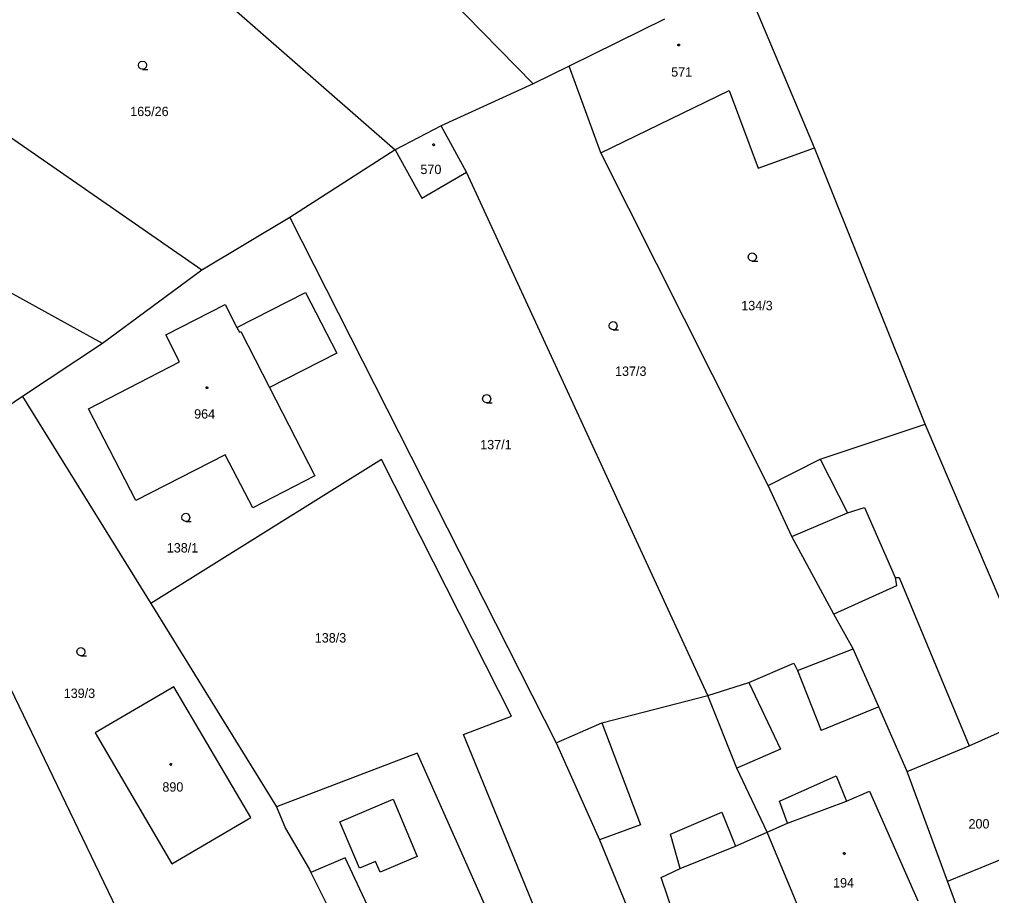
# Model space of a CAD drawing. Extents: x -757994 to -755874, y -1047691 to -1046119.
# Drawn here: x -756617.1 to -756529, y -1046807.2 to -1046727.9 of the extents above; entities that cross this region are included whole.
import ezdxf

# ---------------------------------------------------------------- set-up
doc = ezdxf.new("R2010")
doc.units = 0
doc.layers.add('katastrální mapa', color=7, linetype='Continuous')

msp = doc.modelspace()

# ---------------------------------------------------------------- linework, layer by layer
at = {"layer": 'katastrální mapa'}
for p, q in [((-756606.32, -1046719.31), (-756583.02, -1046739.66)), ((-756581.89, -1046722.04), (-756570.55, -1046733.67)), ((-756545.07, -1046739.46), (-756551.46, -1046724.28)), ((-756558.64, -1046727.81), (-756567.29, -1046732.07)), ((-756567.29, -1046732.07), (-756570.55, -1046733.67)), ((-756564.41, -1046739.94), (-756567.29, -1046732.07)), ((-756570.55, -1046733.67), (-756578.88, -1046737.48)), ((-756600.53, -1046750.55), (-756623.66, -1046734.54)), ((-756564.41, -1046739.94), (-756552.8, -1046734.29)), ((-756552.8, -1046734.29), (-756550.15, -1046741.3)), ((-756578.88, -1046737.48), (-756583.02, -1046739.66)), ((-756576.58, -1046741.67), (-756578.88, -1046737.48)), ((-756583.02, -1046739.66), (-756592.57, -1046745.77)), ((-756583.02, -1046739.66), (-756580.61, -1046744.02)), ((-756550.15, -1046741.3), (-756545.07, -1046739.46)), ((-756535.04, -1046764.48), (-756545.07, -1046739.46)), ((-756549.25, -1046770.05), (-756564.41, -1046739.94)), ((-756580.61, -1046744.02), (-756576.58, -1046741.67)), ((-756554.71, -1046789.06), (-756576.58, -1046741.67)), ((-756609.53, -1046757.2), (-756635.08, -1046743.13)), ((-756592.57, -1046745.77), (-756600.53, -1046750.55)), ((-756592.57, -1046745.77), (-756568.44, -1046793.33)), ((-756600.53, -1046750.55), (-756609.53, -1046757.2)), ((-756597.36, -1046755.74), (-756591.15, -1046752.56)), ((-756591.15, -1046752.56), (-756588.33, -1046758.07)), ((-756603.79, -1046756.41), (-756598.43, -1046753.65)), ((-756598.43, -1046753.65), (-756597.36, -1046755.74)), ((-756602.56, -1046758.86), (-756603.79, -1046756.41)), ((-756597.36, -1046755.74), (-756597.14, -1046756.16)), ((-756597.14, -1046756.16), (-756597, -1046756.09)), ((-756597, -1046756.09), (-756594.4, -1046761.17)), ((-756609.53, -1046757.2), (-756616.78, -1046762)), ((-756588.33, -1046758.07), (-756594.4, -1046761.17)), ((-756610.8, -1046763.1), (-756602.56, -1046758.86)), ((-756594.4, -1046761.17), (-756590.3, -1046769.18)), ((-756616.78, -1046762), (-756624.18, -1046766.9)), ((-756616.78, -1046762), (-756605.17, -1046780.74)), ((-756606.52, -1046771.41), (-756610.8, -1046763.1)), ((-756544.53, -1046767.65), (-756535.04, -1046764.48)), ((-756518.57, -1046803.12), (-756535.04, -1046764.48)), ((-756598.42, -1046767.28), (-756606.52, -1046771.41)), ((-756595.93, -1046772.08), (-756598.42, -1046767.28)), ((-756549.25, -1046770.05), (-756544.53, -1046767.65)), ((-756544.53, -1046767.65), (-756542.08, -1046772.53)), ((-756627.02, -1046769.47), (-756605.13, -1046814.89)), ((-756590.3, -1046769.18), (-756595.93, -1046772.08)), ((-756547.1, -1046774.66), (-756549.25, -1046770.05)), ((-756542.08, -1046772.53), (-756540.52, -1046772.03)), ((-756540.52, -1046772.03), (-756537.75, -1046778.37)), ((-756547.1, -1046774.66), (-756542.08, -1046772.53)), ((-756543.3, -1046781.7), (-756547.1, -1046774.66)), ((-756537.75, -1046778.37), (-756537.39, -1046778.36)), ((-756537.75, -1046778.37), (-756537.64, -1046779.14)), ((-756537.39, -1046778.36), (-756531.04, -1046793.61)), ((-756537.64, -1046779.14), (-756543.3, -1046781.7)), ((-756605.17, -1046780.74), (-756593.77, -1046799.13)), ((-756541.55, -1046784.82), (-756543.3, -1046781.7)), ((-756546.6, -1046786.8), (-756541.55, -1046784.82)), ((-756539.24, -1046790.08), (-756541.55, -1046784.82)), ((-756551, -1046787.88), (-756546.92, -1046786.14)), ((-756546.92, -1046786.14), (-756546.6, -1046786.8)), ((-756546.6, -1046786.8), (-756544.45, -1046792.21)), ((-756603.08, -1046788.27), (-756610.19, -1046792.45)), ((-756596.11, -1046800.11), (-756603.08, -1046788.27)), ((-756554.71, -1046789.06), (-756551, -1046787.88)), ((-756551, -1046787.88), (-756548.13, -1046793.91)), ((-756564.33, -1046791.54), (-756554.71, -1046789.06)), ((-756552.08, -1046795.63), (-756554.71, -1046789.06)), ((-756539.24, -1046790.08), (-756544.45, -1046792.21)), ((-756536.67, -1046795.95), (-756539.24, -1046790.08)), ((-756568.44, -1046793.33), (-756564.33, -1046791.54)), ((-756564.33, -1046791.54), (-756560.81, -1046800.77)), ((-756610.19, -1046792.45), (-756603.25, -1046804.31)), ((-756531.04, -1046793.61), (-756527.33, -1046791.96)), ((-756568.44, -1046793.33), (-756564.54, -1046802.11)), ((-756581.05, -1046794.27), (-756593.77, -1046799.13)), ((-756548.13, -1046793.91), (-756552.08, -1046795.63)), ((-756536.67, -1046795.95), (-756531.04, -1046793.61)), ((-756549.35, -1046801.44), (-756552.08, -1046795.63)), ((-756533.02, -1046805.87), (-756536.67, -1046795.95)), ((-756548.22, -1046798.63), (-756543.11, -1046796.34)), ((-756543.11, -1046796.34), (-756542.17, -1046798.61)), ((-756542.17, -1046798.61), (-756540.07, -1046797.73)), ((-756540.07, -1046797.73), (-756535.71, -1046807.66)), ((-756588.03, -1046800.48), (-756583.2, -1046798.44)), ((-756583.2, -1046798.44), (-756581.04, -1046803.64)), ((-756547.5, -1046800.6), (-756548.22, -1046798.63)), ((-756547.5, -1046800.6), (-756542.17, -1046798.61)), ((-756593.77, -1046799.13), (-756592.97, -1046801.1)), ((-756558.1, -1046801.62), (-756553.45, -1046799.63)), ((-756553.45, -1046799.63), (-756552.2, -1046802.71)), ((-756603.25, -1046804.31), (-756596.11, -1046800.11)), ((-756586.27, -1046804.69), (-756588.03, -1046800.48)), ((-756549.35, -1046801.44), (-756547.5, -1046800.6)), ((-756592.97, -1046801.1), (-756590.8, -1046804.8)), ((-756560.81, -1046800.77), (-756564.54, -1046802.11)), ((-756552.2, -1046802.71), (-756549.35, -1046801.44)), ((-756545.15, -1046811.51), (-756549.35, -1046801.44)), ((-756564.54, -1046802.11), (-756557.5, -1046819.13)), ((-756557.21, -1046804.72), (-756558.1, -1046801.62)), ((-756532.92, -1046805.83), (-756523.59, -1046802)), ((-756557.21, -1046804.72), (-756552.2, -1046802.71)), ((-756587.56, -1046803.75), (-756590.66, -1046805.08)), ((-756585.13, -1046808.98), (-756587.56, -1046803.75)), ((-756584.81, -1046804.07), (-756586.27, -1046804.69)), ((-756584.4, -1046805.04), (-756584.81, -1046804.07)), ((-756581.04, -1046803.64), (-756584.4, -1046805.04)), ((-756590.8, -1046804.8), (-756590.66, -1046805.08)), ((-756558.94, -1046805.54), (-756557.21, -1046804.72)), ((-756590.66, -1046805.08), (-756588.87, -1046808.69)), ((-756555.52, -1046815.57), (-756558.94, -1046805.54)), ((-756533.02, -1046805.87), (-756532.92, -1046805.83)), ((-756531.97, -1046808.74), (-756533.02, -1046805.87))]:
    msp.add_line(p, q, dxfattribs=at)
for points in [[(-756557.35, -1046730.075), (-756557.3, -1046730.085), (-756557.275, -1046730.13), (-756557.265, -1046730.16), (-756557.275, -1046730.205), (-756557.315, -1046730.24), (-756557.35, -1046730.245), (-756557.395, -1046730.23), (-756557.425, -1046730.2), (-756557.435, -1046730.16), (-756557.425, -1046730.115), (-756557.385, -1046730.08)], [(-756579.54, -1046739.115), (-756579.49, -1046739.125), (-756579.465, -1046739.17), (-756579.455, -1046739.2), (-756579.465, -1046739.245), (-756579.505, -1046739.28), (-756579.54, -1046739.285), (-756579.585, -1046739.27), (-756579.615, -1046739.24), (-756579.625, -1046739.2), (-756579.615, -1046739.155), (-756579.575, -1046739.12)], [(-756600.08, -1046761.105), (-756600.03, -1046761.115), (-756600.005, -1046761.16), (-756599.995, -1046761.19), (-756600.005, -1046761.235), (-756600.045, -1046761.27), (-756600.08, -1046761.275), (-756600.125, -1046761.26), (-756600.155, -1046761.23), (-756600.165, -1046761.19), (-756600.155, -1046761.145), (-756600.115, -1046761.11)], [(-756603.35, -1046795.215), (-756603.3, -1046795.225), (-756603.275, -1046795.27), (-756603.265, -1046795.3), (-756603.275, -1046795.345), (-756603.315, -1046795.38), (-756603.35, -1046795.385), (-756603.395, -1046795.37), (-756603.425, -1046795.34), (-756603.435, -1046795.3), (-756603.425, -1046795.255), (-756603.385, -1046795.22)], [(-756542.37, -1046803.275), (-756542.32, -1046803.285), (-756542.295, -1046803.33), (-756542.285, -1046803.36), (-756542.295, -1046803.405), (-756542.335, -1046803.44), (-756542.37, -1046803.445), (-756542.415, -1046803.43), (-756542.445, -1046803.4), (-756542.455, -1046803.36), (-756542.445, -1046803.315), (-756542.405, -1046803.28)]]:
    msp.add_lwpolyline(points, close=True, dxfattribs=at)
for points in [[(-756605.91, -1046732.36), (-756606.1, -1046732.31), (-756606.235, -1046732.175), (-756606.285, -1046731.99), (-756606.235, -1046731.805), (-756606.1, -1046731.67), (-756605.915, -1046731.62), (-756605.73, -1046731.67), (-756605.595, -1046731.805), (-756605.545, -1046731.995), (-756605.595, -1046732.185), (-756605.73, -1046732.32), (-756605.92, -1046732.37), (-756605.42, -1046732.37)], [(-756550.69, -1046749.73), (-756550.88, -1046749.68), (-756551.015, -1046749.545), (-756551.065, -1046749.36), (-756551.015, -1046749.175), (-756550.88, -1046749.04), (-756550.695, -1046748.99), (-756550.51, -1046749.04), (-756550.375, -1046749.175), (-756550.325, -1046749.365), (-756550.375, -1046749.555), (-756550.51, -1046749.69), (-756550.7, -1046749.74), (-756550.2, -1046749.74)], [(-756563.29, -1046755.95), (-756563.48, -1046755.9), (-756563.615, -1046755.765), (-756563.665, -1046755.58), (-756563.615, -1046755.395), (-756563.48, -1046755.26), (-756563.295, -1046755.21), (-756563.11, -1046755.26), (-756562.975, -1046755.395), (-756562.925, -1046755.585), (-756562.975, -1046755.775), (-756563.11, -1046755.91), (-756563.3, -1046755.96), (-756562.8, -1046755.96)], [(-756574.74, -1046762.56), (-756574.93, -1046762.51), (-756575.065, -1046762.375), (-756575.115, -1046762.19), (-756575.065, -1046762.005), (-756574.93, -1046761.87), (-756574.745, -1046761.82), (-756574.56, -1046761.87), (-756574.425, -1046762.005), (-756574.375, -1046762.195), (-756574.425, -1046762.385), (-756574.56, -1046762.52), (-756574.75, -1046762.57), (-756574.25, -1046762.57)], [(-756564.73, -1046822.13), (-756576.84, -1046792.58), (-756572.51, -1046790.92), (-756584.28, -1046767.68), (-756605.17, -1046780.74)], [(-756601.99, -1046773.3), (-756602.18, -1046773.25), (-756602.315, -1046773.115), (-756602.365, -1046772.93), (-756602.315, -1046772.745), (-756602.18, -1046772.61), (-756601.995, -1046772.56), (-756601.81, -1046772.61), (-756601.675, -1046772.745), (-756601.625, -1046772.935), (-756601.675, -1046773.125), (-756601.81, -1046773.26), (-756602, -1046773.31), (-756601.5, -1046773.31)], [(-756611.49, -1046785.46), (-756611.68, -1046785.41), (-756611.815, -1046785.275), (-756611.865, -1046785.09), (-756611.815, -1046784.905), (-756611.68, -1046784.77), (-756611.495, -1046784.72), (-756611.31, -1046784.77), (-756611.175, -1046784.905), (-756611.125, -1046785.095), (-756611.175, -1046785.285), (-756611.31, -1046785.42), (-756611.5, -1046785.47), (-756611, -1046785.47)], [(-756581.05, -1046794.27), (-756574.14, -1046809.83), (-756571.28, -1046814.53), (-756567.75, -1046823.38)]]:
    msp.add_lwpolyline(points, dxfattribs=at)

# ---------------------------------------------------------------- texts
for s, p in [('571', (-756558.036, -1046733.03)), ('165/26', (-756607.027, -1046736.6)), ('570', (-756580.744, -1046741.85)), ('134/3', (-756551.69, -1046754.18)), ('137/3', (-756563.12, -1046760.12)), ('964', (-756601.237, -1046763.99)), ('137/1', (-756575.332, -1046766.77)), ('138/1', (-756603.715, -1046776.11)), ('138/3', (-756590.313, -1046784.26)), ('139/3', (-756613.05, -1046789.28)), ('890', (-756604.114, -1046797.76)), ('200', (-756531.111, -1046801.1)), ('194', (-756543.373, -1046806.44))]:
    msp.add_text(s, height=0.85, dxfattribs=at).set_placement(p)

doc.saveas('drawing.dxf')
